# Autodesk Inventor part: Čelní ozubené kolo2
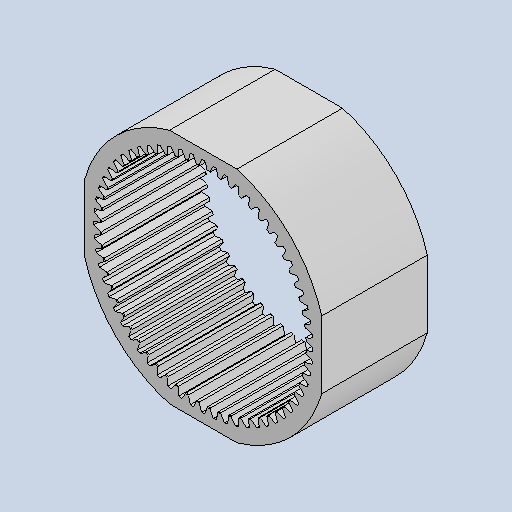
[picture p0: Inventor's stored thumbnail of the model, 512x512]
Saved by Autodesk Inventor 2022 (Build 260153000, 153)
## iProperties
CustomPartVersion: 1
Created: 2025-05
Part Number: Čelní ozubené kolo2
Material: Všeobecné
Document SubType Name: Modeling
Designer: jbart
Categories: <?xml version="1.0" encoding="UTF-16"?> <MemberInstance><Categories><FamilyTemplate><FamilyTemplateParameter ValueType="xs:double" Id="1" ObjectReferenceKey="da
Density: 1 g/cm^3
Appearance: Výchozí
Mass: 5966.28 g
Surface Area: 6901.86 cm^2
Volume: 5966.28 cm^3
Author: jbart
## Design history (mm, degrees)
sketch "Sketch1"
  geometry: C1 r 210 at (0, 0)
  constraints: 1 centre point
  dimensions: "d0" = 420 diameter of C1
extrude "Extrusion1" new body sketch "Sketch1" distance "d1" = 180 (= da_b); taper "d2" = 0 deg
workplane "Work Plane2"
sketch "Sketch2"
  geometry: C1 r 210 at (0, 0) reference; C2 r 180 at (0, 0)
  constraints: 1 centre point, 1 coincident
  dimensions: "d3" = 360 diameter of C2 (= da_d)
feature "Roztečný průměr" sketch "Sketch2" dims "d4" = 10, "d5" = 0
workplane "Work Plane8"
workplane "Work Plane9"
feature "Čelní ozubené kolo" dims "d72" = 0, "da_b" = 180, "da_d" = 360, "da_z" = 600, "da_aw" = 125.36534, "da_da" = 349.09631, "da_df" = 373.75525, "da_dw" = 358.18668, "da_z2" = 180, "da_beta" = 0, "da_lefttooth" = 0, "da_righttooth" = 0, "da_straighttooth" = 10
chamfer "Zkosení1" distance "d60" = 1; stored, may be unused: second distance "d61" = 2, angle "d62" = 45 deg
chamfer "Zkosení2" distance "d64" = 1; stored, may be unused: second distance "d65" = 2, angle "d66" = 45 deg
sketch "Náčrt5"
  geometry: L1 (0, 0)-(0, 50); L2 (-150, 222)-(150, 222); L3 (150, 222)-(150, 202); L4 (150, 202)-(-150, 202); L5 (-150, 202)-(-150, 222)
  constraints: 10 end point, 2 parallel, 1 horizontal, 1 perpendicular, 1 vertical, 1 other
  dimensions: "d67" = 50 distance of L1.start L1.end; "d68" = 300 distance of L3.end L4.end; "d69" = 20 distance of L2.end L3.end; "d70" = 202 distance from line of L1.start L4
extrude "Vysunutí3" cut sketch "Náčrt5" extent not by distance; stored distance "d71" = 0; taper "d72" = 0 deg
pattern_circular "Kruhové pole2" dims angle "d74" = 360 deg
body "Solid1"
body "Srf1"
other parameters: "d16" = 125.36534 (= da_aw), "d17" = 0, "d34" = 3 deg (computed from da_z), "d39" = 0, "d45" = 0, "d47" = 125.36534 (= da_aw), "d50" = 0, "d51" = 0, "d52" = 125.36534 (= da_aw)
